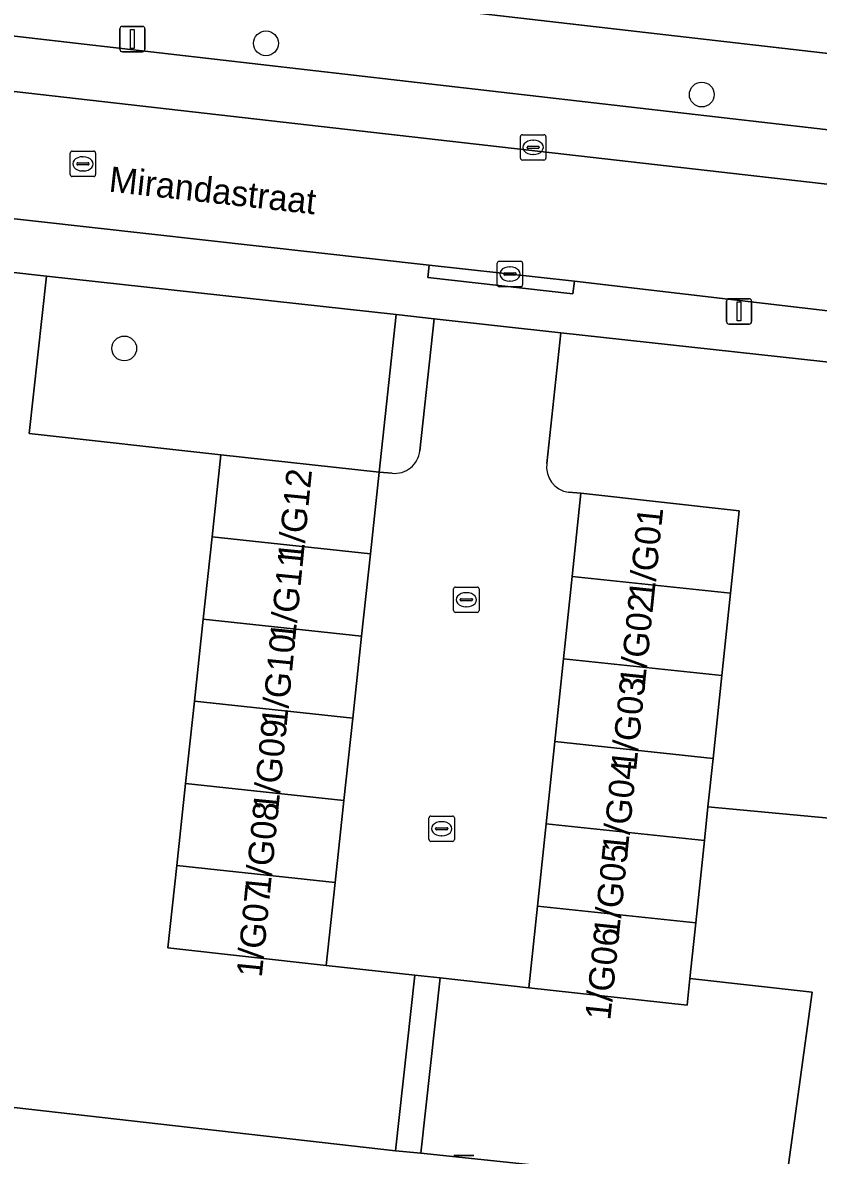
# Model space of a CAD drawing. Extents: x 161928 to 163071, y 386474 to 387428.
# Drawn here: x 162234.98 to 162266.32, y 387001.03 to 387045.64 of the extents above; entities that cross this region are included whole.
import ezdxf

# ---------------------------------------------------------------- set-up
doc = ezdxf.new("R2010")
doc.units = 0
for name, color, linetype in [('IMGEO_Boom', 7, 'Continuous'), ('IMGEO_Erf', 7, 'Continuous'), ('IMGEO_Groenvoorziening', 7, 'Continuous'), ('IMGEO_Haag', 7, 'Continuous'), ('IMGEO_Kolk', 7, 'Continuous'), ('IMGEO_Lichtmast', 7, 'Continuous'), ('IMGEO_Openbare_ruimte_label', 7, 'Continuous'), ('IMGEO_Pand', 7, 'Continuous'), ('IMGEO_Pand_nummerreeks', 7, 'Continuous'), ('IMGEO_Parkeervlak_open', 7, 'Continuous'), ('IMGEO_Rijbaan_lokaal_open', 7, 'Continuous'), ('IMGEO_Rioolput', 7, 'Continuous'), ('IMGEO_Voetpad_open', 7, 'Continuous')]:
    doc.layers.add(name, color=color, linetype=linetype)

msp = doc.modelspace()

# ---------------------------------------------------------------- linework, layer by layer
at = {"layer": 'IMGEO_Boom'}
for centre in [(162244.564, 387044.823), (162261.731, 387042.806), (162238.981, 387032.807)]:
    msp.add_circle(centre, 0.489, dxfattribs=at)
at = {"layer": 'IMGEO_Erf'}
msp.add_lwpolyline([(162202.596, 387051.794), (162288.423, 387041.928), (162292.928, 387041.432)], dxfattribs=at)
at = {"layer": 'IMGEO_Groenvoorziening'}
for points in [[(162235.923, 387035.657), (162229.928, 387036.317), (162229.156, 387029.365), (162229.989, 387029.273), (162227.931, 387010.613), (162206.885, 387012.934), (162207.401, 387017.613), (162200.393, 387018.378), (162199.167, 387006.944), (162231.748, 387003.246), (162249.668, 387001.212), (162250.432, 387008.128), (162246.936, 387008.514), (162240.704, 387009.203), (162241.052, 387012.44), (162241.4, 387015.676), (162241.748, 387018.913), (162242.095, 387022.149), (162242.443, 387025.386), (162242.791, 387028.622), (162235.238, 387029.457)], [(162249.69, 387034.141), (162235.923, 387035.657), (162235.238, 387029.457), (162242.791, 387028.622), (162249.023, 387027.933)], [(162261.271, 387000), (162265.004, 386999.609), (162265.057, 387000), (162266.075, 387007.463), (162261.265, 387007.999), (162261.154, 387006.944), (162254.923, 387007.632), (162251.426, 387008.018), (162250.663, 387001.111)]]:
    msp.add_lwpolyline(points, close=True, dxfattribs=at)
for points in [[(162249.69, 387034.141), (162249.023, 387027.933)], [(162251.186, 387033.976), (162249.69, 387034.141)], [(162250.623, 387028.775), (162251.186, 387033.976)], [(162291.581, 387029.555), (162256.179, 387033.419), (162255.624, 387028.283)], [(162249.023, 387027.933), (162249.53, 387027.895)], [(162256.479, 387027.144), (162256.966, 387027.106), (162263.197, 387026.418), (162262.856, 387023.172), (162262.516, 387019.927), (162262.174, 387016.665), (162261.973, 387014.754), (162266.747, 387014.304), (162267.077, 387016.83), (162271.046, 387016.413), (162271.412, 387019.683), (162270.574, 387019.777), (162270.689, 387020.81), (162271.548, 387020.714), (162271.979, 387024.574)]]:
    msp.add_lwpolyline(points, dxfattribs=at)
for centre, radius, start, end in [((162249.639, 387028.878), 0.989, 263.6609, 354.0159), ((162256.625, 387028.144), 1.011, 172.0949, 261.6932)]:
    msp.add_arc(centre, radius, start, end, dxfattribs=at)
at = {"layer": 'IMGEO_Haag'}
for points in [[(162249.69, 387034.141), (162249.023, 387027.933)], [(162251.186, 387033.976), (162249.69, 387034.141)], [(162250.623, 387028.775), (162251.186, 387033.976)], [(162249.023, 387027.933), (162249.53, 387027.895)]]:
    msp.add_lwpolyline(points, dxfattribs=at)
msp.add_arc((162249.639, 387028.878), 0.989, 263.6609, 354.0159, dxfattribs=at)
at = {"layer": 'IMGEO_Kolk'}
for p, q in [((162254.663, 387041.224), (162255.515, 387041.224)), ((162254.588, 387040.298), (162254.588, 387041.15)), ((162254.847, 387040.718), (162254.847, 387040.73)), ((162254.89, 387040.767), (162255.288, 387040.767)), ((162255.076, 387041.004), (162255.101, 387041.004)), ((162255.331, 387040.73), (162255.331, 387040.718)), ((162255.589, 387041.15), (162255.589, 387040.298)), ((162255.285, 387040.681), (162254.887, 387040.681)), ((162255.099, 387040.444), (162255.074, 387040.444)), ((162255.515, 387040.224), (162254.663, 387040.224)), ((162253.673, 387035.312), (162253.673, 387036.164)), ((162253.748, 387036.238), (162254.6, 387036.238)), ((162254.161, 387036.018), (162254.186, 387036.018)), ((162254.674, 387036.164), (162254.674, 387035.312)), ((162253.932, 387035.732), (162253.932, 387035.744)), ((162254.37, 387035.695), (162253.972, 387035.695)), ((162253.975, 387035.781), (162254.373, 387035.781)), ((162254.184, 387035.458), (162254.159, 387035.458)), ((162254.416, 387035.744), (162254.416, 387035.732)), ((162254.6, 387035.238), (162253.748, 387035.238)), ((162251.956, 387022.484), (162251.956, 387023.336)), ((162252.031, 387023.41), (162252.883, 387023.41)), ((162252.957, 387023.336), (162252.957, 387022.484)), ((162252.215, 387022.904), (162252.215, 387022.916)), ((162252.258, 387022.953), (162252.656, 387022.953)), ((162252.444, 387023.19), (162252.469, 387023.19)), ((162252.699, 387022.916), (162252.699, 387022.904)), ((162252.653, 387022.867), (162252.255, 387022.867)), ((162252.467, 387022.63), (162252.442, 387022.63)), ((162252.883, 387022.41), (162252.031, 387022.41)), ((162250.986, 387013.466), (162250.986, 387014.318)), ((162251.061, 387014.392), (162251.913, 387014.392)), ((162251.474, 387014.172), (162251.499, 387014.172)), ((162251.987, 387014.318), (162251.987, 387013.466)), ((162251.245, 387013.886), (162251.245, 387013.898)), ((162251.683, 387013.849), (162251.285, 387013.849)), ((162251.288, 387013.935), (162251.686, 387013.935)), ((162251.497, 387013.612), (162251.472, 387013.612)), ((162251.729, 387013.898), (162251.729, 387013.886)), ((162251.913, 387013.392), (162251.061, 387013.392))]:
    msp.add_line(p, q, dxfattribs=at)
for points in [[(162254.663, 387041.224), (162255.515, 387041.224)], [(162254.588, 387040.298), (162254.588, 387041.15)], [(162255.589, 387041.15), (162255.589, 387040.298)], [(162255.515, 387040.224), (162254.663, 387040.224)], [(162253.673, 387035.312), (162253.673, 387036.164)], [(162253.748, 387036.238), (162254.6, 387036.238)], [(162254.674, 387036.164), (162254.674, 387035.312)], [(162254.6, 387035.238), (162253.748, 387035.238)], [(162251.956, 387022.484), (162251.956, 387023.336)], [(162252.031, 387023.41), (162252.883, 387023.41)], [(162252.957, 387023.336), (162252.957, 387022.484)], [(162252.883, 387022.41), (162252.031, 387022.41)], [(162250.986, 387013.466), (162250.986, 387014.318)], [(162251.061, 387014.392), (162251.913, 387014.392)], [(162251.987, 387014.318), (162251.987, 387013.466)], [(162251.913, 387013.392), (162251.061, 387013.392)]]:
    msp.add_lwpolyline(points, dxfattribs=at)
for centre, radius, start, end in [((162254.665, 387041.148), 0.0765, 91.552, 178.448), ((162254.665, 387041.148), 0.0765, 91.552, 178.448), ((162255.513, 387041.148), 0.0765, 1.552, 88.448), ((162255.513, 387041.148), 0.0765, 1.552, 88.448), ((162254.887, 387040.727), 0.0403, 85.8775, 175.7526), ((162255.292, 387040.729), 0.0386, 1.7309, 96.639), ((162254.665, 387040.3), 0.0765, 181.552, 268.448), ((162254.665, 387040.3), 0.0765, 181.552, 268.448), ((162254.884, 387040.717), 0.0366, 178.938, 274.7102), ((162255.288, 387040.724), 0.043, 264.8664, 352.4533), ((162255.513, 387040.3), 0.0765, 271.552, 358.448), ((162255.513, 387040.3), 0.0765, 271.552, 358.448), ((162253.75, 387036.162), 0.0765, 91.552, 178.448), ((162253.75, 387036.162), 0.0765, 91.552, 178.448), ((162254.598, 387036.162), 0.0765, 1.552, 88.448), ((162254.598, 387036.162), 0.0765, 1.552, 88.448), ((162253.972, 387035.741), 0.0403, 85.8775, 175.7526), ((162253.969, 387035.731), 0.0366, 178.938, 274.7102), ((162254.373, 387035.738), 0.043, 264.8664, 352.4533), ((162254.377, 387035.743), 0.0386, 1.7309, 96.639), ((162253.75, 387035.314), 0.0765, 181.552, 268.448), ((162253.75, 387035.314), 0.0765, 181.552, 268.448), ((162254.598, 387035.314), 0.0765, 271.552, 358.448), ((162254.598, 387035.314), 0.0765, 271.552, 358.448), ((162252.033, 387023.334), 0.0765, 91.552, 178.448), ((162252.033, 387023.334), 0.0765, 91.552, 178.448), ((162252.881, 387023.334), 0.0765, 1.552, 88.448), ((162252.881, 387023.334), 0.0765, 1.552, 88.448), ((162252.255, 387022.913), 0.0403, 85.8775, 175.7526), ((162252.252, 387022.903), 0.0366, 178.938, 274.7102), ((162252.656, 387022.91), 0.043, 264.8664, 352.4533), ((162252.66, 387022.915), 0.0386, 1.7309, 96.639), ((162252.033, 387022.486), 0.0765, 181.552, 268.448), ((162252.033, 387022.486), 0.0765, 181.552, 268.448), ((162252.881, 387022.486), 0.0765, 271.552, 358.448), ((162252.881, 387022.486), 0.0765, 271.552, 358.448), ((162251.063, 387014.316), 0.0765, 91.552, 178.448), ((162251.063, 387014.316), 0.0765, 91.552, 178.448), ((162251.911, 387014.316), 0.0765, 1.552, 88.448), ((162251.911, 387014.316), 0.0765, 1.552, 88.448), ((162251.285, 387013.895), 0.0403, 85.8775, 175.7526), ((162251.282, 387013.885), 0.0366, 178.938, 274.7102), ((162251.686, 387013.892), 0.043, 264.8664, 352.4533), ((162251.69, 387013.897), 0.0386, 1.7309, 96.639), ((162251.063, 387013.468), 0.0765, 181.552, 268.448), ((162251.063, 387013.468), 0.0765, 181.552, 268.448), ((162251.911, 387013.468), 0.0765, 271.552, 358.448), ((162251.911, 387013.468), 0.0765, 271.552, 358.448)]:
    msp.add_arc(centre, radius, start, end, dxfattribs=at)
for centre, major_axis, ratio, start_param, end_param in [((162255.075, 387040.724), (-0.387, 0.002), 0.722429, 4.712389, 7.853982), ((162255.1, 387040.724), (-0.39, 0.002), 0.717154, 1.570796, 4.712389), ((162254.16, 387035.738), (-0.387, 0.002), 0.722429, 4.712389, 7.853982), ((162254.185, 387035.738), (-0.39, 0.002), 0.717154, 1.570796, 4.712389), ((162252.443, 387022.91), (-0.387, 0.002), 0.722429, 4.712389, 7.853982), ((162252.468, 387022.91), (-0.39, 0.002), 0.717154, 1.570796, 4.712389), ((162251.473, 387013.892), (-0.387, 0.002), 0.722429, 4.712389, 7.853982), ((162251.498, 387013.892), (-0.39, 0.002), 0.717154, 1.570796, 4.712389)]:
    msp.add_ellipse(centre, major_axis=major_axis, ratio=ratio, start_param=start_param, end_param=end_param, dxfattribs=at)
at = {"layer": 'IMGEO_Lichtmast'}
for p, q in [((162238.809, 387044.588), (162238.809, 387045.388)), ((162238.809, 387045.388), (162238.809, 387044.588)), ((162238.909, 387045.488), (162239.699, 387045.488)), ((162239.699, 387045.488), (162238.909, 387045.488)), ((162239.799, 387045.388), (162239.799, 387044.588)), ((162239.799, 387044.588), (162239.799, 387045.388)), ((162239.699, 387044.488), (162238.909, 387044.488)), ((162238.909, 387044.488), (162239.699, 387044.488)), ((162262.704, 387033.866), (162262.704, 387034.666)), ((162262.704, 387034.666), (162262.704, 387033.866)), ((162262.804, 387034.766), (162263.594, 387034.766)), ((162263.594, 387034.766), (162262.804, 387034.766)), ((162263.694, 387034.666), (162263.694, 387033.866)), ((162263.694, 387033.866), (162263.694, 387034.666)), ((162263.594, 387033.766), (162262.804, 387033.766)), ((162262.804, 387033.766), (162263.594, 387033.766)), ((162251.968, 387001.032), (162252.758, 387001.032)), ((162252.758, 387001.032), (162251.968, 387001.032))]:
    msp.add_line(p, q, dxfattribs=at)
for points in [[(162239.229, 387045.363), (162239.379, 387045.363), (162239.379, 387044.613), (162239.229, 387044.613), (162239.229, 387045.363)], [(162263.124, 387034.641), (162263.274, 387034.641), (162263.274, 387033.891), (162263.124, 387033.891), (162263.124, 387034.641)]]:
    msp.add_lwpolyline(points, dxfattribs=at)
for centre, start, end in [((162238.909, 387045.388), 90, 180), ((162238.909, 387045.388), 90, 180), ((162239.699, 387045.388), 0, 90), ((162239.699, 387045.388), 360, 90), ((162238.909, 387044.588), 180, 270), ((162238.909, 387044.588), 180, 270), ((162239.699, 387044.588), 270, 0), ((162239.699, 387044.588), 270, 0), ((162262.804, 387034.666), 90, 180), ((162262.804, 387034.666), 90, 180), ((162263.594, 387034.666), 0, 90), ((162263.594, 387034.666), 360, 90), ((162262.804, 387033.866), 180, 270), ((162262.804, 387033.866), 180, 270), ((162263.594, 387033.866), 270, 0), ((162263.594, 387033.866), 270, 0)]:
    msp.add_arc(centre, 0.1, start, end, dxfattribs=at)
at = {"layer": 'IMGEO_Pand'}
for points in [[(162249.023, 387027.933), (162242.791, 387028.622), (162242.443, 387025.386), (162248.677, 387024.716)], [(162256.622, 387023.826), (162262.856, 387023.172), (162263.197, 387026.418), (162256.966, 387027.106)], [(162248.677, 387024.716), (162242.443, 387025.386), (162242.095, 387022.149), (162248.329, 387021.479)], [(162256.281, 387020.581), (162262.516, 387019.927), (162262.856, 387023.172), (162256.622, 387023.826)], [(162247.982, 387018.243), (162248.329, 387021.479), (162242.095, 387022.149), (162241.748, 387018.913)], [(162262.174, 387016.665), (162262.516, 387019.927), (162256.281, 387020.581), (162255.941, 387017.335)], [(162241.748, 387018.913), (162241.4, 387015.676), (162247.634, 387015.006), (162247.982, 387018.243)], [(162262.174, 387016.665), (162255.941, 387017.335), (162255.6, 387014.089), (162261.835, 387013.435), (162261.973, 387014.754)], [(162247.634, 387015.006), (162241.4, 387015.676), (162241.052, 387012.44), (162247.286, 387011.77)], [(162255.26, 387010.844), (162261.495, 387010.19), (162261.835, 387013.435), (162255.6, 387014.089)], [(162247.286, 387011.77), (162241.052, 387012.44), (162240.704, 387009.203), (162246.936, 387008.514)], [(162254.923, 387007.632), (162261.154, 387006.944), (162261.265, 387007.999), (162261.495, 387010.19), (162255.26, 387010.844)]]:
    msp.add_lwpolyline(points, close=True, dxfattribs=at)
at = {"layer": 'IMGEO_Parkeervlak_open'}
for points in [[(162289.168, 387038.822), (162288.165, 387038.944), (162213.325, 387047.577)], [(162209.297, 387045.816), (162292.807, 387036.295)]]:
    msp.add_lwpolyline(points, dxfattribs=at)
at = {"layer": 'IMGEO_Rijbaan_lokaal_open'}
for points in [[(162293.928, 387036.193), (162292.807, 387036.295), (162209.297, 387045.816)], [(162184.213, 387043.306), (162187.102, 387043.012), (162194.737, 387042.328), (162202.099, 387041.543), (162210.343, 387040.623), (162217.274, 387039.85), (162223.604, 387039.144), (162231.014, 387038.317), (162250.997, 387036.088), (162256.711, 387035.451), (162290.902, 387031.456), (162293.855, 387031.139)], [(162255.624, 387028.283), (162256.179, 387033.419), (162251.186, 387033.976), (162250.623, 387028.775)], [(162249.53, 387027.895), (162249.023, 387027.933), (162248.677, 387024.716), (162248.329, 387021.479), (162247.982, 387018.243), (162247.634, 387015.006), (162247.286, 387011.77), (162246.936, 387008.514), (162250.432, 387008.128), (162251.426, 387008.018), (162254.923, 387007.632), (162255.26, 387010.844), (162255.6, 387014.089), (162255.941, 387017.335), (162256.281, 387020.581), (162256.622, 387023.826), (162256.966, 387027.106), (162256.479, 387027.144)]]:
    msp.add_lwpolyline(points, dxfattribs=at)
for centre, radius, start, end in [((162249.639, 387028.878), 0.989, 263.6609, 354.0159), ((162256.625, 387028.144), 1.011, 172.0949, 261.6932)]:
    msp.add_arc(centre, radius, start, end, dxfattribs=at)
at = {"layer": 'IMGEO_Rioolput'}
for p, q in [((162236.853, 387039.651), (162236.853, 387040.503)), ((162236.928, 387040.577), (162237.78, 387040.577)), ((162237.341, 387040.357), (162237.366, 387040.357)), ((162237.854, 387040.503), (162237.854, 387039.651)), ((162237.112, 387040.071), (162237.112, 387040.083)), ((162237.55, 387040.034), (162237.152, 387040.034)), ((162237.155, 387040.12), (162237.553, 387040.12)), ((162237.596, 387040.083), (162237.596, 387040.071)), ((162237.78, 387039.577), (162236.928, 387039.577)), ((162237.364, 387039.797), (162237.339, 387039.797))]:
    msp.add_line(p, q, dxfattribs=at)
for points in [[(162236.853, 387039.651), (162236.853, 387040.503)], [(162236.928, 387040.577), (162237.78, 387040.577)], [(162237.854, 387040.503), (162237.854, 387039.651)], [(162237.78, 387039.577), (162236.928, 387039.577)]]:
    msp.add_lwpolyline(points, dxfattribs=at)
for centre, radius, start, end in [((162236.93, 387040.501), 0.0765, 91.552, 178.448), ((162236.93, 387040.501), 0.0765, 91.552, 178.448), ((162237.778, 387040.501), 0.0765, 1.552, 88.448), ((162237.778, 387040.501), 0.0765, 1.552, 88.448), ((162237.152, 387040.08), 0.0403, 85.8775, 175.7526), ((162237.149, 387040.07), 0.0366, 178.938, 274.7102), ((162237.553, 387040.077), 0.043, 264.8664, 352.4533), ((162237.557, 387040.082), 0.0386, 1.7309, 96.639), ((162236.93, 387039.653), 0.0765, 181.552, 268.448), ((162236.93, 387039.653), 0.0765, 181.552, 268.448), ((162237.778, 387039.653), 0.0765, 271.552, 358.448), ((162237.778, 387039.653), 0.0765, 271.552, 358.448)]:
    msp.add_arc(centre, radius, start, end, dxfattribs=at)
for centre, major_axis, ratio, start_param, end_param in [((162237.34, 387040.077), (-0.387, 0.002), 0.722429, 4.712389, 7.853982), ((162237.365, 387040.077), (-0.39, 0.002), 0.717154, 1.570796, 4.712389)]:
    msp.add_ellipse(centre, major_axis=major_axis, ratio=ratio, start_param=start_param, end_param=end_param, dxfattribs=at)
at = {"layer": 'IMGEO_Voetpad_open'}
for points in [[(162292.928, 387041.432), (162288.423, 387041.928), (162202.596, 387051.794)], [(162213.325, 387047.577), (162288.165, 387038.944), (162289.168, 387038.822)], [(162293.551, 387027.906), (162293.855, 387031.139), (162290.902, 387031.456), (162256.711, 387035.451), (162256.658, 387034.963), (162250.943, 387035.595), (162250.997, 387036.088), (162231.014, 387038.317), (162230.961, 387037.807), (162223.551, 387038.637), (162223.604, 387039.144), (162217.274, 387039.85), (162217.222, 387039.346), (162210.292, 387040.122), (162210.343, 387040.623), (162202.099, 387041.543)], [(162193.838, 387039.967), (162197.397, 387039.614), (162202.53, 387039.39), (162210.868, 387038.451), (162216.749, 387037.817), (162224.147, 387037.026), (162229.928, 387036.317), (162235.923, 387035.657), (162249.69, 387034.141), (162251.186, 387033.976), (162256.179, 387033.419), (162291.581, 387029.555)], [(162287.87, 386996.318), (162266.57, 386999.408), (162265.004, 386999.609), (162261.271, 387000), (162250.663, 387001.111), (162249.668, 387001.212), (162231.748, 387003.246), (162199.167, 387006.944)]]:
    msp.add_lwpolyline(points, dxfattribs=at)
for points in [[(162256.711, 387035.451), (162250.997, 387036.088), (162250.943, 387035.595), (162256.658, 387034.963)], [(162266.57, 386999.408), (162266.654, 387000), (162267.521, 387006.143), (162268.663, 387006.033), (162269.648, 387014.855), (162270.857, 387014.719), (162271.046, 387016.413), (162267.077, 387016.83), (162266.747, 387014.304), (162261.973, 387014.754), (162261.835, 387013.435), (162261.495, 387010.19), (162261.265, 387007.999), (162266.075, 387007.463), (162265.057, 387000), (162265.004, 386999.609)], [(162250.432, 387008.128), (162249.668, 387001.212), (162250.663, 387001.111), (162251.426, 387008.018)]]:
    msp.add_lwpolyline(points, close=True, dxfattribs=at)

# ---------------------------------------------------------------- texts
at = {"layer": 'IMGEO_Openbare_ruimte_label'}
msp.add_text('Mirandastraat', height=1, rotation=353.6851, dxfattribs=at).set_placement((162238.348, 387038.986))
at = {"layer": 'IMGEO_Pand_nummerreeks'}
for s, rotation, p in [('1/G12', 84.3344, (162246.022, 387024.387)), ('1/G01', 84.0754, (162259.841, 387022.879)), ('1/G11', 84.3344, (162245.71, 387021.245)), ('1/G02', 84.0754, (162259.488, 387019.475)), ('1/G10', 84.3344, (162245.376, 387017.881)), ('1/G03', 84.0754, (162259.147, 387016.193)), ('1/G09', 84.3344, (162245.044, 387014.527)), ('1/G04', 84.0754, (162258.806, 387012.905)), ('1/G08', 84.3344, (162244.721, 387011.276)), ('1/G05', 84.0754, (162258.465, 387009.616)), ('1/G07', 84.3344, (162244.398, 387008.016)), ('1/G06', 84.0754, (162258.124, 387006.328))]:
    msp.add_text(s, height=1, rotation=rotation, dxfattribs=at).set_placement(p)

doc.saveas('drawing.dxf')
